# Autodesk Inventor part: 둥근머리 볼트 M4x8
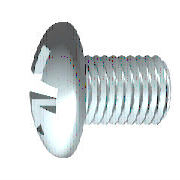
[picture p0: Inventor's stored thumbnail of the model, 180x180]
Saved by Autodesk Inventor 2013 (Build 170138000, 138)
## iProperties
Created: 2012-02
Part Number: 둥근머리 볼트 M4x8
Material: 강철, 연강
Description: 십자 오목 머리 나사
Document SubType Name: Modeling
Standard: KS B 1023
Designer: mduedu
Standards Organization: KS
Language: ko-KR
Size Designation: A  M 4 x 8 - H
Categories: <MemberInstance><Categories><Category DisplayName="조임쇠" InternalName="e4da775c-781d-43d5-af7c-5136215cf5a6" Mnemonic="FSTN"><Category DisplayName="볼트" InternalN
Density: 7.86 g/cm^3
Mass: 1.61931 g
Surface Area: 2.62079 cm^2
Volume: 0.206019 cm^3
IsCustomPart: 1
Author: mduedu
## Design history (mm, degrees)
workplane "Work Plane3"
sketch "스케치2"
  geometry: L1 (-5.374, 0)-(5.374, 0) reference; L2 (0, -5.374)-(0, 5.374) reference; L3 (0, 2.3)-(0, 0); L4 (0, 0)-(2.3, 0); L5 (0, 0)-(2.714, 2.714); L6 (0.311, 2.279)-(0.392, 0.703); L7 (2.279, 0.311)-(0.703, 0.392); L8 (0.311, -2.279)-(0.392, -0.703); L9 (2.279, -0.311)-(0.703, -0.392); L10 (-0.311, 2.279)-(-0.392, 0.703); L11 (-2.279, 0.311)-(-0.703, 0.392); L12 (-2.279, -0.311)-(-0.703, -0.392); L13 (-0.311, -2.279)-(-0.392, -0.703); A1 r 0.69 centre (0, 0) between (0.69, 0) and (0, 0.69); A2 r 2.3 centre (0, 0) between (2.3, 0) and (2.279, 0.311); A3 r 2.3 centre (0, 0) between (0.311, 2.279) and (0, 2.3); A4 r 2.3 centre (0, 0) between (2.279, 0.311) and (0.311, 2.279); A5 r 2.3 centre (0, 0) between (0, -2.3) and (0.311, -2.279); A6 r 2.3 centre (0, 0) between (0.311, -2.279) and (2.279, -0.311); A7 r 2.3 centre (0, 0) between (2.279, -0.311) and (2.3, 0); A8 r 2.3 centre (0, 0) between (-2.279, 0.311) and (-2.3, 0); A9 r 2.3 centre (0, 0) between (-0.311, 2.279) and (-2.279, 0.311); A10 r 2.3 centre (0, 0) between (0, 2.3) and (-0.311, 2.279); A11 r 2.3 centre (0, 0) between (-2.3, 0) and (-2.279, -0.311); A12 r 2.3 centre (0, 0) between (-2.279, -0.311) and (-0.311, -2.279); A13 r 2.3 centre (0, 0) between (-0.311, -2.279) and (0, -2.3); A14 r 0.805 centre (0, 0) between (0.805, 0) and (0, 0.805); A15 r 0.328 centre (0.72, 0.72) between (0.392, 0.703) and (0.703, 0.392); A16 r 0.328 centre (0.72, -0.72) between (0.703, -0.392) and (0.392, -0.703); A17 r 0.328 centre (-0.72, 0.72) between (-0.703, 0.392) and (-0.392, 0.703); A18 r 0.328 centre (-0.72, -0.72) between (-0.392, -0.703) and (-0.703, -0.392); 1 further point
  constraints: 38 point on circle, 22 end point, 19 symmetric about line, 18 centre point, 4 coincident, 3 collinear, 3 point on line, 3 tangent, 1 perpendicular, 21 other
  dimensions: "d4" = 45 deg angle of L5 L4; "d5" = 1.38 diameter of A1 (= 0.3 x SDM); "d6" = 4.6 diameter of A4 (= SDM); "d7" = 0.3115 distance from line of L6.start L3 (= 0.5 x SBR); "d14" = 1.61 diameter of A14 (= 0.35 x SDM)
extrude "슬롯" join sketch "스케치2" taper "d15" = 5 deg; stored distance "d54" = 10
revolve "절단부" stored, may be unused: angle "d56" = 90 deg
revolve "본체" stored, may be unused: angle "d18" = 90 deg
workplane "Work Plane1"
body "Solid1"
sketch "스케치1"
  geometry: L1 (8, 0)-(8, 2); L2 (8, 2)-(1.4, 2); L3 (3.962, 5.08)-(3.962, 5.08); L4 (-3.1, 0)-(-3.1, 3.729); L5 (-2.744, 2.122)-(-1.498, 1.501); L6 (-1.498, 1.501)-(-0.7, 0); L7 (-0.7, 0)-(8, 0); L8 (-5.687, 0)-(10.281, 0) reference; L9 (0, -1.016)-(0, 6.096) reference; L10 (-2.744, 2.122)-(-3.1, 2.3); L11 (-1.846, 3.839)-(-3.1, 3.729); L12 (-1.846, 3.839)-(0, 4); L13 (0, 4)-(0, 1.785); L14 (0, 1.785)-(0.971, 1.785); L15 (0.971, 1.785)-(1.4, 2); L16 (1.4, 2)-(0, 2); A1 r 6.5 centre (3.4, 0) between (-1.846, 3.839) and (-3.1, 0)
  constraints: 28 end point, 5 point on line, 4 collinear, 4 point on circle, 3 parallel, 2 perpendicular, 1 centre point, 1 horizontal, 1 tangent
  dimensions: "d1" = 4 diameter of L2 L7 (= GD); "d2" = 2.4 distance from line of L6.end L4 (= STI); "d11" = 4.6 diameter of L10.end L7 (= SDM); "d12" = 62 deg angle of L6 L7; "d13" = 26.5 deg angle of L5 L7; "d17" = 8 diameter of L12.end L7 (= KOD); "d19" = 5 deg angle of L12 L7 (= KEWI); "d20" = 3.1 distance between parallel lines of L4 L13 (= KOH); "d21" = 6.5 radius of A1 (= KR); "d23" = 3.5705 diameter of L14 L7 (= BDM); "d24" = 6.6 distance of L1.end L2.end (= GEL); "d25" = 0.42941 horizontal distance of L14.end L2.end (= GAL); "d28" = 8 distance between parallel lines of L1 L13 (= NLG)
fillet "모깎기1" dims "d29" = 1.6 (= RR)
fillet "모깎기2" dims "d16" = 0.1246 (= 0.2 x SBR)
feature "스레드" dims "d8" = 6.6 (= GEL), "d9" = 0
chamfer "모따기1" distance "d26" = 0.42941 (= -0.5 x SPD + 0.5 x GD); stored, may be unused: second distance "d27" = 0.42952 (computed from GUL), angle "d78" = 45 deg
other parameters: "GD" = 4 (= NND) [user parameter; used in 2 equation terms], "NLG" = 8 [user parameter; used in 1 equation term], "GEL" = 6.6 [user parameter; used in 2 equation terms], "KOD" = 8 [user parameter; used in 1 equation term], "KOH" = 3.1 [user parameter; used in 2 equation terms], "SDM" = 4.6 [user parameter; used in 4 equation terms], "STI" = 2.4 [user parameter; used in 1 equation term], "SBR" = 0.623 [user parameter; used in 2 equation terms], "GAL" = 0.42941 (= 0.61345 x PTC) [user parameter; used in 1 equation term], "SPD" = 3.14117 (= NND - 1.2269 x PTC) [user parameter; used in 1 equation term], "KEWI" = 5 deg [user parameter; used in 1 equation term], "d3" = -3.1 (= -KOH), "d10" = 0, "KR" = 6.5 [user parameter; used in 1 equation term], "BDM" = 3.5705 [user parameter; used in 1 equation term], "GUL" = 0.42941 (= 0.61345 x PTC) [user parameter; used in 1 equation term], "RR" = 1.6 [user parameter; used in 1 equation term], "d79" = 0, "d80" = 0, "PTC" = 0.7 [user parameter; used in 5 equation terms], "THREADDIA" = 4 [user parameter; used in 1 equation term], "TOA" = 30 deg [user parameter], "TPU" = 14.28571 (computed from PTC) [user parameter], "NND" = 4 [user parameter; used in 2 equation terms], "GD1" = 3.14117 (= THREADDIA - 1.2269 x PTC) [user parameter]
